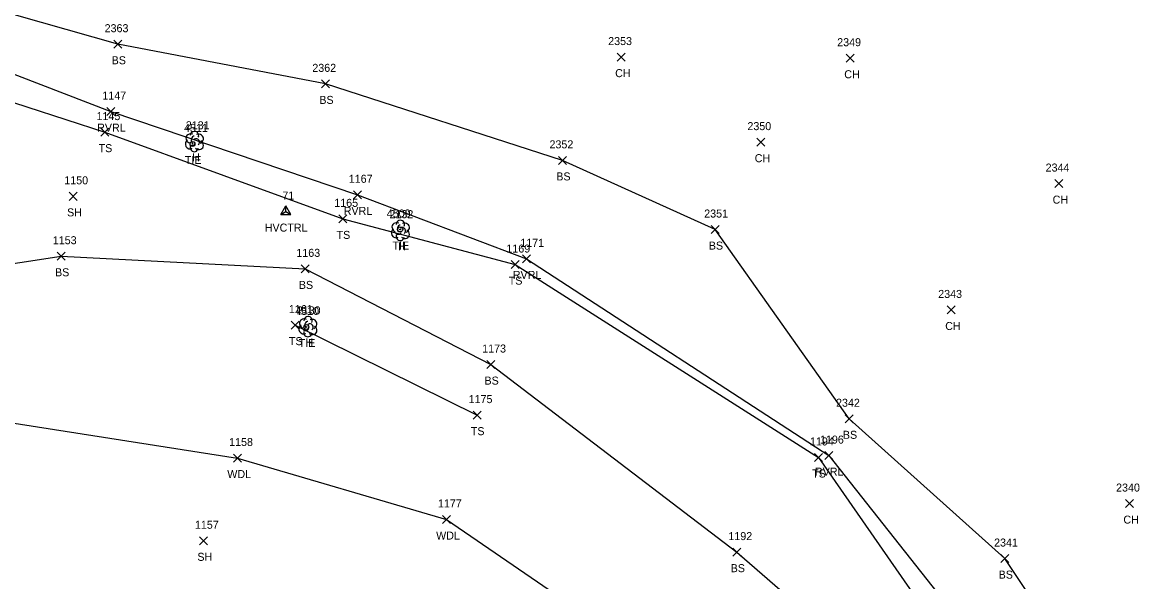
# Model space of a CAD drawing. Extents: x 1509053 to 1511576, y 400838 to 402572.
# Drawn here: x 1509430.5 to 1509710.5, y 402095.5 to 402235 of the extents above; entities that cross this region are included whole.
import ezdxf

# ---------------------------------------------------------------- set-up
doc = ezdxf.new("R2010")
doc.units = 0
for name, color, linetype in [('C_A', 7, 'Continuous'), ('C_I', 7, 'Continuous'), ('CBP', 7, 'Continuous'), ('CPSM', 7, 'Continuous'), ('L_A', 7, 'Continuous'), ('L_I', 7, 'Continuous'), ('L_TIC', 7, 'Continuous'), ('LAWA', 7, 'Continuous'), ('LAWE', 7, 'Continuous'), ('LELB', 7, 'Continuous'), ('LTD', 7, 'Continuous')]:
    doc.layers.add(name, color=color, linetype=linetype)

msp = doc.modelspace()

# ---------------------------------------------------------------- linework, layer by layer
at = {"layer": 'CBP'}
for centre, radius in [((1509472.95, 402204.72), 0.625), ((1509472.95, 402204.72), 0.0833), ((1509524.83, 402183.39), 0.625), ((1509524.83, 402183.39), 0.0833), ((1509501.39, 402159.06), 0.625), ((1509501.39, 402159.06), 0.0833)]:
    msp.add_circle(centre, radius, dxfattribs=at)
at = {"layer": 'CPSM'}
for p, q in [((1509495.05, 402187.14), (1509496.3, 402189.3)), ((1509497.55, 402187.14), (1509496.3, 402189.3)), ((1509496.3, 402187.86), (1509496.3, 402189.3)), ((1509495.05, 402187.14), (1509496.3, 402187.86)), ((1509495.05, 402187.14), (1509497.55, 402187.14)), ((1509496.3, 402187.86), (1509496.3, 402187.86)), ((1509496.3, 402187.86), (1509497.55, 402187.14))]:
    msp.add_line(p, q, dxfattribs=at)
at = {"layer": 'L_TIC'}
for points in [[(1509453.31, 402228.61), (1509455.31, 402230.61)], [(1509455.31, 402228.61), (1509453.31, 402230.61)], [(1509579.04, 402225.4), (1509581.04, 402227.4)], [(1509581.04, 402225.4), (1509579.04, 402227.4)], [(1509636.26, 402225.12), (1509638.26, 402227.12)], [(1509638.26, 402225.12), (1509636.26, 402227.12)], [(1509505.19, 402218.72), (1509507.19, 402220.72)], [(1509507.19, 402218.72), (1509505.19, 402220.72)], [(1509451.56, 402211.8), (1509453.56, 402213.8)], [(1509453.56, 402211.8), (1509451.56, 402213.8)], [(1509450.09, 402206.68), (1509452.09, 402208.68)], [(1509452.09, 402206.68), (1509450.09, 402208.68)], [(1509613.9, 402204.18), (1509615.9, 402206.18)], [(1509615.9, 402204.18), (1509613.9, 402206.18)], [(1509564.38, 402199.63), (1509566.38, 402201.63)], [(1509566.38, 402199.63), (1509564.38, 402201.63)], [(1509688.31, 402193.84), (1509690.31, 402195.84)], [(1509690.31, 402193.84), (1509688.31, 402195.84)], [(1509442.13, 402190.66), (1509444.13, 402192.66)], [(1509444.13, 402190.66), (1509442.13, 402192.66)], [(1509513.16, 402191.04), (1509515.16, 402193.05)], [(1509515.16, 402191.04), (1509513.16, 402193.05)], [(1509509.53, 402185.04), (1509511.53, 402187.04)], [(1509511.53, 402185.04), (1509509.53, 402187.04)], [(1509602.47, 402182.37), (1509604.47, 402184.37)], [(1509604.47, 402182.37), (1509602.47, 402184.37)], [(1509439.17, 402175.72), (1509441.17, 402177.72)], [(1509441.17, 402175.72), (1509439.17, 402177.72)], [(1509500.07, 402172.56), (1509502.07, 402174.56)], [(1509502.07, 402172.56), (1509500.07, 402174.56)], [(1509552.53, 402173.63), (1509554.53, 402175.63)], [(1509554.53, 402173.63), (1509552.53, 402175.63)], [(1509555.38, 402175.06), (1509557.38, 402177.06)], [(1509557.38, 402175.06), (1509555.38, 402177.06)], [(1509661.48, 402162.31), (1509663.48, 402164.31)], [(1509663.48, 402162.31), (1509661.48, 402164.31)], [(1509497.62, 402158.54), (1509499.62, 402160.54)], [(1509499.62, 402158.54), (1509497.62, 402160.54)], [(1509546.44, 402148.69), (1509548.44, 402150.69)], [(1509548.44, 402148.69), (1509546.44, 402150.69)], [(1509543.05, 402136.07), (1509545.05, 402138.07)], [(1509545.05, 402136.07), (1509543.05, 402138.07)], [(1509635.96, 402135.16), (1509637.96, 402137.16)], [(1509637.96, 402135.16), (1509635.96, 402137.16)], [(1509483.22, 402125.37), (1509485.22, 402127.37)], [(1509485.22, 402125.37), (1509483.22, 402127.37)], [(1509628.32, 402125.51), (1509630.32, 402127.51)], [(1509630.32, 402125.51), (1509628.32, 402127.51)], [(1509630.87, 402125.97), (1509632.87, 402127.97)], [(1509632.87, 402125.97), (1509630.87, 402127.97)], [(1509705.99, 402114), (1509707.99, 402116)], [(1509707.99, 402114), (1509705.99, 402116)], [(1509535.38, 402110.03), (1509537.38, 402112.04)], [(1509537.38, 402110.03), (1509535.38, 402112.04)], [(1509474.68, 402104.72), (1509476.68, 402106.72)], [(1509476.68, 402104.72), (1509474.68, 402106.72)], [(1509607.94, 402101.89), (1509609.94, 402103.89)], [(1509609.94, 402101.89), (1509607.94, 402103.89)], [(1509674.87, 402100.28), (1509676.87, 402102.28)], [(1509676.87, 402100.28), (1509674.87, 402102.28)]]:
    msp.add_lwpolyline(points, dxfattribs=at)
at = {"layer": 'LAWA'}
msp.add_lwpolyline([(1509076.57, 402183.15), (1509127.79, 402182.33), (1509173.6, 402169.45), (1509206.41, 402183.98), (1509219.47, 402177.73), (1509276.12, 402165.35), (1509324.31, 402150.34), (1509333.92, 402141.66), (1509378.2, 402140.76), (1509422.99, 402135.87), (1509484.22, 402126.37), (1509536.38, 402111.03), (1509587.67, 402075.95), (1509623.1, 402040.21), (1509661.3, 402001.82), (1509687.76, 401950.54), (1509742.09, 401890.27)], dxfattribs=at)
at = {"layer": 'LAWE'}
msp.add_lwpolyline([(1509105.87, 402324.24), (1509166.85, 402316.84), (1509211.49, 402305.13), (1509268.21, 402284.91), (1509312.96, 402259.07), (1509356.2, 402241.45), (1509401.11, 402232.66), (1509452.56, 402212.8), (1509514.16, 402192.04), (1509556.38, 402176.06), (1509631.87, 402126.97), (1509661.73, 402089.31), (1509701.86, 402034.14), (1509721.26, 402000.81), (1509742.13, 401921.74), (1509766.75, 401859.14), (1509782.51, 401819.75), (1509797.91, 401768.02), (1509814.1, 401723.17), (1509831.98, 401671.21)], dxfattribs=at)
at = {"layer": 'LELB'}
for points in [[(1509893.6, 401622.33), (1509860.64, 401660.7), (1509835.46, 401719.88), (1509820.45, 401775.67), (1509804.55, 401821.18), (1509793.58, 401877.47), (1509769.39, 401921.13), (1509750.31, 401995.31), (1509714.67, 402043.06), (1509675.87, 402101.28), (1509636.96, 402136.16), (1509603.47, 402183.37), (1509565.38, 402200.63), (1509506.19, 402219.72), (1509454.31, 402229.61), (1509409.3, 402242.42), (1509343.87, 402268.78), (1509286.85, 402299.31), (1509229.32, 402329.05), (1509168.38, 402334.88), (1509111.42, 402354.71)], [(1509268.21, 402284.91), (1509314.49, 402254.64), (1509356.98, 402231.85), (1509402.27, 402223.46), (1509451.09, 402207.68), (1509510.53, 402186.04), (1509553.53, 402174.63), (1509629.32, 402126.51), (1509658.3, 402084.82), (1509698.84, 402034.54), (1509720.34, 401997.13), (1509738.81, 401919.7), (1509762.85, 401861.64), (1509780.24, 401817.03), (1509795.72, 401767.1), (1509811.96, 401722.66)], [(1509386.28, 402168.51), (1509440.17, 402176.72), (1509501.07, 402173.56), (1509547.44, 402149.69), (1509608.94, 402102.89), (1509648.8, 402068.27), (1509684.12, 402026.81), (1509704.75, 401988.35), (1509738.81, 401919.7)], [(1509498.62, 402159.53), (1509544.05, 402137.07)]]:
    msp.add_lwpolyline(points, dxfattribs=at)
at = {"layer": 'LTD'}
for p, q in [((1509473.4, 402205.39), (1509473.4, 402205.39)), ((1509473.4, 402205.39), (1509473.4, 402205.39)), ((1509524.85, 402183.2), (1509524.85, 402183.2)), ((1509524.85, 402183.2), (1509524.85, 402183.2)), ((1509501.77, 402159.21), (1509501.77, 402159.21)), ((1509501.77, 402159.21), (1509501.77, 402159.21))]:
    msp.add_line(p, q, dxfattribs=at)
for centre in [(1509473.45, 402206.82), (1509524.9, 402184.64), (1509501.82, 402160.64)]:
    msp.add_arc(centre, 1.05, 335.5272, 180.9563, dxfattribs=at)
for centre, major_axis, ratio, start_param, end_param in [((1509472.32, 402204.68), (0.58, -1.04), 0.959034, 3.141593, 6.283185), ((1509472.61, 402206.06), (1.21, -0.51), 0.895232, 1.570796, 4.712389), ((1509473.19, 402205.85), (-0.208, -0.792), 0.645439, 3.141593, 6.283185), ((1509473.9, 402205.22), (-0.5, 0.667), 0.989748, 3.141593, 6.283185), ((1509474.4, 402204.56), (-1.09, 0.79), 0.841452, 1.570796, 4.712389), ((1509474.44, 402205.97), (-1.14, -0.48), 0.949671, 1.570796, 4.712389), ((1509473.4, 402203.89), (0.26, 1.06), 0.942809, 1.570796, 4.712389), ((1509472.94, 402204.64), (-0.625, -0.083), 0.423636, 0, 3.141593), ((1509523.77, 402182.5), (0.58, -1.04), 0.959034, 3.141593, 6.283185), ((1509524.06, 402183.87), (1.21, -0.51), 0.895232, 1.570796, 4.712389), ((1509524.65, 402183.66), (-0.208, -0.792), 0.645439, 3.141593, 6.283185), ((1509525.35, 402183.04), (-0.5, 0.667), 0.989748, 3.141593, 6.283185), ((1509525.85, 402182.37), (-1.09, 0.79), 0.841452, 1.570796, 4.712389), ((1509525.9, 402183.79), (-1.14, -0.48), 0.949671, 1.570796, 4.712389), ((1509524.85, 402181.7), (0.26, 1.06), 0.942809, 1.570796, 4.712389), ((1509524.4, 402182.45), (-0.625, -0.083), 0.423636, 0, 3.141593), ((1509500.98, 402159.88), (1.21, -0.51), 0.895232, 1.570796, 4.712389), ((1509501.56, 402159.67), (-0.208, -0.792), 0.645439, 3.141593, 6.283185), ((1509502.81, 402159.79), (-1.14, -0.48), 0.949671, 1.570796, 4.712389), ((1509500.69, 402158.5), (0.58, -1.04), 0.959034, 3.141593, 6.283185), ((1509501.77, 402157.71), (0.26, 1.06), 0.942809, 1.570796, 4.712389), ((1509501.31, 402158.46), (-0.625, -0.083), 0.423636, 0, 3.141593), ((1509502.27, 402159.04), (-0.5, 0.667), 0.989748, 3.141593, 6.283185), ((1509502.77, 402158.38), (-1.09, 0.79), 0.841452, 1.570796, 4.712389)]:
    msp.add_ellipse(centre, major_axis=major_axis, ratio=ratio, start_param=start_param, end_param=end_param, dxfattribs=at)

# ---------------------------------------------------------------- texts
at = {"layer": 'C_A'}
for s, p in [('TIE', (1509471.03, 402199.72)), ('HVCTRL', (1509490.99, 402182.86)), ('TIE', (1509522.91, 402178.39)), ('TIE', (1509499.47, 402154.06))]:
    msp.add_text(s, height=2, dxfattribs=at).set_placement(p)
at = {"layer": 'C_I'}
for s, p in [('4511', (1509470.83, 402207.72)), ('71', (1509495.4, 402190.86)), ('4509', (1509521.48, 402186.39)), ('4510', (1509498.61, 402162.06))]:
    msp.add_text(s, height=2, dxfattribs=at).set_placement(p)
at = {"layer": 'L_A'}
for s, p in [('BS', (1509452.75, 402224.61)), ('CH', (1509578.53, 402221.4)), ('CH', (1509635.75, 402221.12)), ('BS', (1509504.63, 402214.72)), ('RVRL', (1509449.13, 402207.8)), ('TS', (1509449.5, 402202.68)), ('H', (1509472.84, 402200.39)), ('CH', (1509613.39, 402200.18)), ('BS', (1509563.82, 402195.63)), ('CH', (1509687.8, 402189.84)), ('SH', (1509441.62, 402186.66)), ('RVRL', (1509510.72, 402187.04)), ('TS', (1509508.94, 402181.04)), ('H', (1509524.29, 402178.2)), ('BS', (1509601.91, 402178.37)), ('BS', (1509438.61, 402171.71)), ('RVRL', (1509552.95, 402171.06)), ('BS', (1509499.51, 402168.56)), ('TS', (1509551.94, 402169.63)), ('CH', (1509660.97, 402158.31)), ('TS', (1509497.03, 402154.53)), ('H', (1509501.2, 402154.21)), ('BS', (1509545.88, 402144.69)), ('TS', (1509542.46, 402132.07)), ('BS', (1509635.4, 402131.16)), ('WDL', (1509481.64, 402121.37)), ('TS', (1509627.73, 402121.51)), ('RVRL', (1509628.43, 402121.97)), ('CH', (1509705.48, 402110)), ('WDL', (1509533.8, 402106.03)), ('SH', (1509474.17, 402100.72)), ('BS', (1509607.38, 402097.89)), ('BS', (1509674.31, 402096.28))]:
    msp.add_text(s, height=2, dxfattribs=at).set_placement(p)
at = {"layer": 'L_I'}
for s, p in [('2363', (1509451, 402232.61)), ('2353', (1509576.78, 402229.4)), ('2349', (1509633.99, 402229.12)), ('2362', (1509502.88, 402222.72)), ('1147', (1509450.44, 402215.8)), ('1145', (1509448.97, 402210.68)), ('2131', (1509471.28, 402208.39)), ('2350', (1509611.56, 402208.18)), ('2352', (1509562.12, 402203.63)), ('2344', (1509686.05, 402197.84)), ('1167', (1509511.98, 402195.04)), ('1150', (1509440.92, 402194.66)), ('1165', (1509508.36, 402189.04)), ('2132', (1509522.16, 402186.2)), ('2351', (1509600.77, 402186.37)), ('1153', (1509438.05, 402179.71)), ('1171', (1509554.82, 402179.06)), ('1163', (1509498.89, 402176.56)), ('1169', (1509551.35, 402177.63)), ('2343', (1509659.22, 402166.31)), ('1161', (1509497.01, 402162.53)), ('2130', (1509498.99, 402162.21)), ('1173', (1509545.31, 402152.69)), ('1175', (1509541.92, 402140.07)), ('2342', (1509633.7, 402139.16)), ('1158', (1509482.1, 402129.37)), ('1194', (1509627.19, 402129.51)), ('1196', (1509629.69, 402129.97)), ('2340', (1509703.65, 402118)), ('1177', (1509534.25, 402114.03)), ('1157', (1509473.55, 402108.72)), ('1192', (1509606.81, 402105.89)), ('2341', (1509673.18, 402104.28))]:
    msp.add_text(s, height=2, dxfattribs=at).set_placement(p)

doc.saveas('drawing.dxf')
